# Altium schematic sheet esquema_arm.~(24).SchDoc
size A4
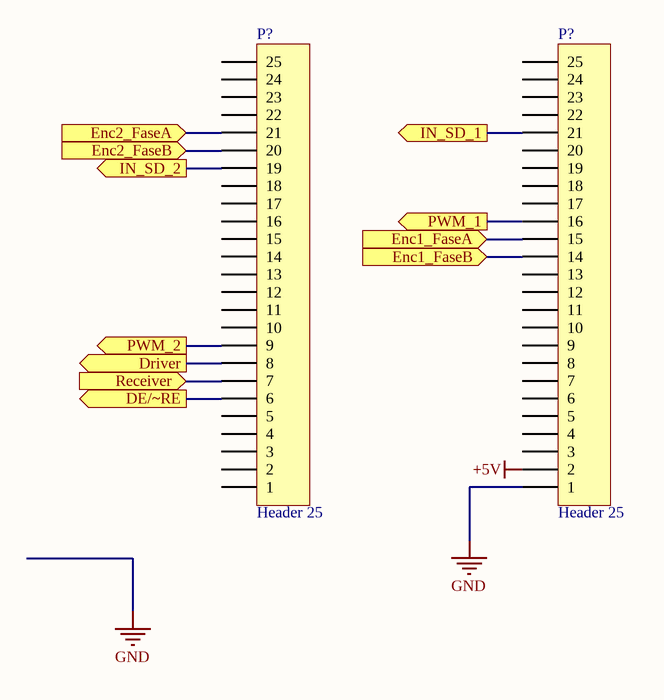
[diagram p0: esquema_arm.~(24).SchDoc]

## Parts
(Parts that share a designator on the sheet are numbered #1, #2 ... from top to bottom, then left to right.)
P?#1  Header 25  [HDR1X25]
P?#2  Header 25  [HDR1X25]

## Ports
DE/~RE (out), Driver (out), Enc1_FaseA (in), Enc1_FaseB (in), Enc2_FaseA (in), Enc2_FaseB (in), IN_SD_1 (out), IN_SD_2 (out), PWM_1 (out), PWM_2 (out), Receiver (in)

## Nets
+5V: P?#2.2
GND: P?#2.1
DE/~RE: P?#1.6 ; port DE/~RE
Driver: P?#1.8 ; port Driver
Enc1_FaseA: P?#2.15 ; port Enc1_FaseA
Enc1_FaseB: P?#2.14 ; port Enc1_FaseB
Enc2_FaseA: P?#1.21 ; port Enc2_FaseA
Enc2_FaseB: P?#1.20 ; port Enc2_FaseB
IN_SD_1: P?#2.21 ; port IN_SD_1
IN_SD_2: P?#1.19 ; port IN_SD_2
PWM_1: P?#2.16 ; port PWM_1
PWM_2: P?#1.9 ; port PWM_2
Receiver: P?#1.7 ; port Receiver

Not connected (* = marked no-connect by the designer): P?#1 1 2 3 4 5 10 11 12 13 14 15 16 17 18 22 23 24 25; P?#2 3 4 5 6 7 8 9 10 11 12 13 17 18 19 20 22 23 24 25

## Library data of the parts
P?#1 P?#2 = Header 25: Header, 25-Pin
